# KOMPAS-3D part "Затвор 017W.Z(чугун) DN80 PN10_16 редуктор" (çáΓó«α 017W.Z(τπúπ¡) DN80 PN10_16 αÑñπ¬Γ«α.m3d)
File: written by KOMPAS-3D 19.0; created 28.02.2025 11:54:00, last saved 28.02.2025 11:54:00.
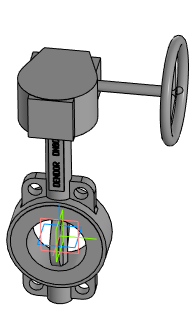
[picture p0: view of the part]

Document properties: Автор: Евгений; Полное имя файла: Затвор 017W.Z(чугун) DN80 PN10_16 редуктор.a3d

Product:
- Part/product: Затвор 017W.Z(чугун) DN80 PN10_16 редуктор
    Масса: 11.2513

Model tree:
1. Операция без истории:1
